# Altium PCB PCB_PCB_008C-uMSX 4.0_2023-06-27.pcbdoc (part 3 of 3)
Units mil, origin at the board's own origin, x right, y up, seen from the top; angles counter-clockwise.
Board outline 14478.11 x 5217.07 mil, 2 copper layers (Top Layer, Bottom Layer); 184 components, 339 nets, 1501 pads, 946 vias.
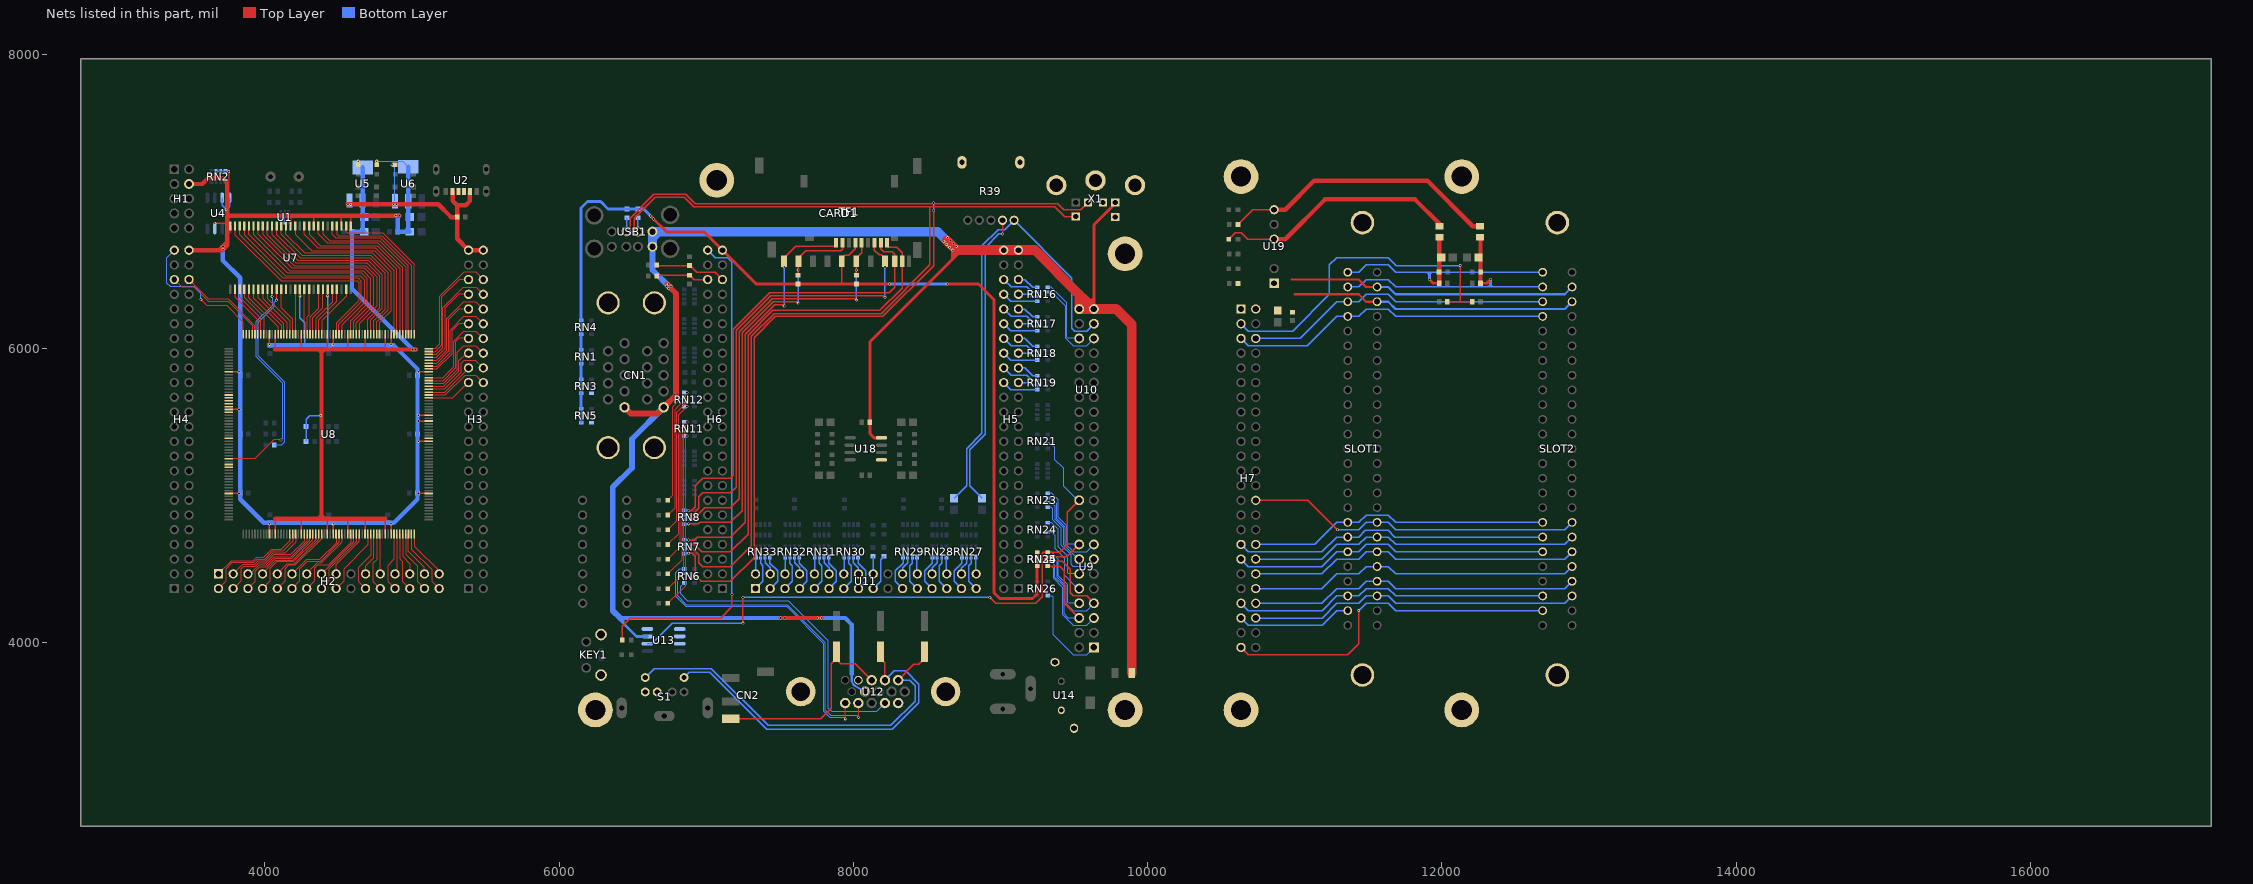
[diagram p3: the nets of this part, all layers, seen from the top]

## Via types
v1: diameter 20, hole 12, Top Layer to Bottom Layer, 944 vias
v2: diameter 24, hole 12, Top Layer to Bottom Layer, 2 vias

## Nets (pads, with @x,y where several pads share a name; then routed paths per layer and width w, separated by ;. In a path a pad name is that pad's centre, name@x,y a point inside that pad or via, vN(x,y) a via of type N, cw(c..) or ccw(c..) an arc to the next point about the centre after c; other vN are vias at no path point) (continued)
IO/163: H3.29 H5.30 RN19.1 U8.163 | length 561
  Top Layer w6: U8.163@5114.14,5663.11 5276.92,5663.11 5380.86,5767.05 H3.29@5385,5767.05
  Bottom Layer w10: H5.30@9022.01,5767.05 9069.25,5719.81 RN19.1@9249.57,5719.81
IO/164: H3.30 H5.29 RN19.2 U8.164 | length 581.3
  Top Layer w6: U8.164@5114.14,5682.8 5226.51,5682.8 5360.76,5817.05 5435,5817.05 H3.30@5485,5767.05
  Bottom Layer w10: H5.29@9122.01,5767.05 9192.01,5767.05 9207.76,5751.3 RN19.2@9249.57,5751.3
IO/165: H3.31 H5.32 RN19.3 U8.165 | length 603.3
  Top Layer w6: U8.165@5114.14,5702.48 5223.57,5702.48 5385,5863.91 H3.31@5385,5867.05
  Bottom Layer w10: H5.32@9022.01,5867.05 9072.01,5817.05 9180,5817.05 9214.25,5782.8 RN19.3@9249.57,5782.8
IO/166: H3.32 H5.31 RN19.4 U8.166 | length 658.4
  Top Layer w6: U8.166@5114.14,5722.17 5220.63,5722.17 5331,5832.54 5331,5895.22 5352.83,5917.05 5435,5917.05 H3.32@5485,5867.05
  Bottom Layer w10: H5.31@9122.01,5867.05 9165,5867.05 9217.76,5814.29 RN19.4@9249.57,5814.29
IO/167: H3.33 H5.34 RN18.1 U8.167 | length 653.5
  Top Layer w6: U8.167@5114.14,5741.85 5217.68,5741.85 5319,5843.17 5319,5915.19 5370.86,5967.05 H3.33@5385,5967.05
  Bottom Layer w10: H5.34@9022.01,5967.05 9069.25,5919.81 RN18.1@9249.57,5919.81
IO/168: H3.34 H5.33 RN18.2 U8.168 | length 700.8
  Top Layer w6: U8.168@5114.14,5761.54 5214.74,5761.54 5307,5853.79 5307,5972.08 5351.97,6017.05 5435,6017.05 H3.34@5485,5967.05
  Bottom Layer w10: H5.33@9122.01,5967.05 9192.01,5967.05 9207.76,5951.3 RN18.2@9249.57,5951.3
IO/169: H3.35 H5.36 RN18.3 U8.169 | length 756.4
  Top Layer w6: U8.169@5114.14,5781.22 5211.8,5781.22 5295,5864.42 5295,6043.11 5318.94,6067.05 H3.35@5385,6067.05
  Bottom Layer w10: H5.36@9022.01,6067.05 9072.01,6017.05 9180,6017.05 9214.25,5982.8 RN18.3@9249.57,5982.8
IO/170: H3.36 H5.35 RN18.4 U8.170 | length 773.3
  Top Layer w6: U8.170@5114.14,5800.91 5208.86,5800.91 5283,5875.05 5283,6048.08 5351.97,6117.05 5435,6117.05 H3.36@5485,6067.05
  Bottom Layer w10: H5.35@9122.01,6067.05 9165,6067.05 9217.76,6014.29 RN18.4@9249.57,6014.29
IO/173: H3.37 H5.38 RN17.1 U8.173 | length 737.8
  Top Layer w6: U8.173@5114.14,5859.96 5169.88,5859.96 5271,5961.08 5271,6119.11 5318.94,6167.05 H3.37@5385,6167.05
  Bottom Layer w10: H5.38@9022.01,6167.05 9069.25,6119.81 RN17.1@9249.57,6119.81
IO/174: H3.38 H5.37 RN17.2 U8.174 | length 755.1
  Top Layer w6: U8.174@5114.14,5879.65 5167.6,5879.65 5259,5971.05 5259,6124.08 5351.97,6217.05 5435,6217.05 H3.38@5485,6167.05
  Bottom Layer w10: H5.37@9122.01,6167.05 9192.01,6167.05 9207.76,6151.3 RN17.2@9249.57,6151.3
IO/175: H3.39 H5.40 RN17.3 U8.175 | length 812.2
  Top Layer w6: U8.175@5114.14,5899.33 5167.28,5899.33 5247,5979.05 5247,6195.11 5318.94,6267.05 H3.39@5385,6267.05
  Bottom Layer w10: H5.40@9022.01,6267.05 9072.01,6217.05 9180,6217.05 9214.25,6182.8 RN17.3@9249.57,6182.8
IO/176: H3.40 H5.39 RN17.4 U8.176 | length 830.6
  Top Layer w6: U8.176@5114.14,5919.02 5166.97,5919.02 5235,5987.05 5235,6200.08 5351.97,6317.05 5435,6317.05 H3.40@5485,6267.05
  Bottom Layer w10: H5.39@9122.01,6267.05 9165,6267.05 9217.76,6214.29 RN17.4@9249.57,6214.29
IO/177: H3.41 H5.42 RN16.1 U8.177 | length 856
  Top Layer w6: U8.177@5114.14,5938.7 5164.68,5938.7 5223,5997.02 5223,6271.11 5318.94,6367.05 H3.41@5385,6367.05
  Bottom Layer w10: H5.42@9022.01,6367.05 9069.25,6319.81 RN16.1@9249.57,6319.81
IO/178: H3.42 H5.41 RN16.2 U8.178 | length 871.9
  Top Layer w6: U8.178@5114.14,5958.39 5164.37,5958.39 5211,6005.02 5211,6276.08 5348.97,6414.05 5438,6414.05 H3.42@5485,6367.05
  Bottom Layer w10: H5.41@9122.01,6367.05 9192.01,6367.05 9207.76,6351.3 RN16.2@9249.57,6351.3
IO/179: H3.43 H5.44 RN16.3 U8.179 | length 928.6
  Top Layer w6: U8.179@5114.14,5978.07 5160.05,5978.07 5199,6017.02 5199,6346.08 5319.97,6467.05 H3.43@5385,6467.05
  Bottom Layer w10: H5.44@9022.01,6467.05 9072.01,6417.05 9180,6417.05 9214.25,6382.8 RN16.3@9249.57,6382.8
IO/180: H3.44 H5.43 RN16.4 U8.180 | length 945.7
  Top Layer w6: U8.180@5114.14,5997.76 5158.74,5997.76 5187,6026.02 5187,6351.05 5352,6516.05 5436,6516.05 H3.44@5485,6467.05
  Bottom Layer w10: H5.43@9122.01,6467.05 9165,6467.05 9217.76,6414.29 RN16.4@9249.57,6414.29
IORQ: H7.38 RN24.5 SLOT1.11 SLOT2.11 U9.12 | length 2748.5
  Bottom Layer w6: RN24.5@9320.43,4814.29 9347.76,4814.29 9392.03,4770.02 9392.03,4650.93 9456,4586.96 9456,4473.05 9462,4467.05 U9.12@9535,4467.05
  Bottom Layer w10: H7.38@10735,4467.05 11185,4467.05 11285,4567.05 11435,4567.05 11485.03,4617.08 SLOT1.11@11560,4617.08 11634.97,4617.08 11685,4567.05 12834.97,4567.05 SLOT2.11@12885,4617.08
KCLK: R14.1 RN7.5 USB1.7 X1.1 | length 7481.1
  Top Layer w10: USB1.7@6457.61,6793.1 6482.61,6818.1 6482.61,6884.66 6645,7047.05 6860,7047.05 6925,6982.05 9389.99,6982.05 9429.99,6942.05 9546.01,6942.05 X1.1@9595.01,6991.05 ; v1(6880,4607.05) 6905,4607.05 6925,4587.05 6925,4457.05 6965,4417.05 7165,4417.05 7325,4577.05 7325,6072.05 7470,6217.05 8200,6217.05 8545,6562.05 v1(8545,6937.05)
  Bottom Layer w10: USB1.7@6457.61,6793.1 6460,6795.49 R14.1@6460,6887.39 ; RN7.5@6849.56,4604.81 6851.81,4607.05 v1(6880,4607.05) ; v1(8545,6937.05) v1(8545,6987.05)
KDAT: R15.1 RN7.6 USB1.6 X1.6 | length 7140.9
  Top Layer w10: USB1.6@6536.41,6793.1 6511.41,6818.1 6511.41,6883.46 6655,7027.05 6850,7027.05 6915,6962.05 9370,6962.05 9437,6895.05 X1.6@9512.01,6895.05 ; v1(6880,4637.05) 6910,4637.05 6950,4597.05 6950,4542.05 6975,4517.05 7165,4517.05 7305,4657.05 7305,6080.33 7460.86,6236.19 8189.14,6236.19 8520,6567.05 8520,6962.05
  Bottom Layer w10: R15.1@6535,6887.39 6535,6794.51 USB1.6@6536.41,6793.1 ; RN7.6@6849.56,4636.3 6850.31,4637.05 v1(6880,4637.05)
LED1: LED5.2 RN12.8 | length 786.3
  Top Layer w6: LED5.2@6739.5,4966.85 6773,5000.35 6773,5602.72 v1(6869.56,5699.29)
LED2: LED6.2 RN12.7 | length 854.8
  Top Layer w6: LED6.2@6739.5,4866.85 6785,4912.35 6785,5583.23 v1(6869.56,5667.8)
LED3: LED7.2 RN12.6 | length 923.3
  Top Layer w6: LED7.2@6739.5,4766.85 6797,4824.35 6797,5563.73 v1(6869.56,5636.3)
LED4: LED8.2 RN12.5 | length 991.8
  Top Layer w6: LED8.2@6739.5,4666.85 6809,4736.35 6809,5544.24 v1(6869.56,5604.81)
LED5: LED9.2 RN11.8 | length 986.3
  Top Layer w6: LED9.2@6739.5,4566.85 6821,4648.35 6821,5450.72 v1(6869.56,5499.29)
LED6: LED10.2 RN11.7 | length 1054.8
  Top Layer w6: LED10.2@6739.5,4466.85 6833,4560.35 6833,5431.23 v1(6869.56,5467.8)
LED7: LED11.2 RN11.6 | length 1123.3
  Top Layer w6: LED11.2@6739.5,4366.85 6845,4472.35 6845,5411.73 v1(6869.56,5436.3)
LED8: LED12.2 RN11.5 | length 1191.8
  Top Layer w6: LED12.2@6739.5,4266.85 6857,4384.35 6857,5392.24 v1(6869.56,5404.81)
M1: H7.40 RN24.7 SLOT1.9 SLOT2.9 U9.10 | length 2747.2
  Bottom Layer w6: RN24.7@9320.43,4751.3 9346.96,4751.3 9368.03,4730.22 9368.03,4640.99 9432,4577.02 9432,4461.56 9526.51,4367.05 U9.10@9535,4367.05
  Bottom Layer w10: H7.40@10735,4367.05 11185,4367.05 11285,4467.05 11435,4467.05 11485.03,4517.08 SLOT1.9@11560,4517.08 11634.97,4517.08 11685,4467.05 12834.97,4467.05 SLOT2.9@12885,4517.08
MA0: U7.23 U8.203 | length 1409.9
  Top Layer w6: U7.23@3891.95,6832.05 3891.95,6774.13 4156.03,6510.05 4657.91,6510.05 4696,6471.96 4696,6302.14 4582.64,6188.77 U8.203@4582.64,6096.18
MA1: U7.24 U8.206 | length 1435.6
  Top Layer w6: U7.24@3859.97,6832.05 3859.97,6772.08 4139,6493.05 4647.94,6493.05 4676.5,6464.49 4676.5,6309.61 4523.57,6156.68 U8.206@4523.57,6096.18
MA2: U7.25 U8.207 | length 1442.2
  Top Layer w6: U7.25@3828.95,6832.05 3828.95,6773.1 4125,6477.05 4636.97,6477.05 4657,6457.02 4657,6317.08 4503.9,6163.97 U8.207@4503.9,6096.18
MA3: U7.26 U8.208 | length 1450.4
  Top Layer w6: U7.26@3796.95,6832.05 3796.95,6773.13 4110.03,6460.05 4627,6460.05 4637.5,6449.55 4637.5,6324.55 4484.2,6171.25 U8.208@4484.2,6096.18
MA4: U7.29 U8.235 | length 370.4
  Top Layer w6: U7.29@3797,6402.05 3797,6350.05 3952.72,6194.33 U8.235@3952.72,6096.18
MA5: U7.30 U8.234 | length 365.3
  Top Layer w6: U7.30@3829,6402.05 3829,6348.05 3972.41,6204.64 U8.234@3972.41,6096.18
MA6: U7.31 U8.233 | length 360.6
  Top Layer w6: U7.31@3859.97,6402.05 3859.97,6347.08 3992.09,6214.96 U8.233@3992.09,6096.18
MA7: U7.32 U8.228 | length 388.1
  Top Layer w6: U7.32@3892,6402.05 3892,6345.05 4090.51,6146.53 U8.228@4090.51,6096.18
MA8: U7.33 U8.227 | length 383.4
  Top Layer w6: U7.33@3923,6402.05 3923,6344.05 4110.19,6156.85 U8.227@4110.19,6096.18
MA9: U7.34 U8.226 | length 378.3
  Top Layer w6: U7.34@3954.97,6402.05 3954.97,6342.08 4129.89,6167.16 U8.226@4129.89,6096.18
MA10: U7.22 U8.202 | length 1404.2
  Top Layer w6: U7.22@3923,6832.05 3923,6775.05 4171,6527.05 4667.88,6527.05 4718,6476.93 4718,6297.17 4602.31,6181.48 U8.202@4602.31,6096.18
MA11: U7.35 U8.225 | length 373.6
  Top Layer w6: U7.35@3986.05,6402.05 3986.05,6341 4149.56,6177.48 U8.225@4149.56,6096.18
MA12: U7.36 U8.224 | length 368.5
  Top Layer w6: U7.36@4018,6402.05 4018,6339.05 4169.26,6187.79 U8.224@4169.26,6096.18
MBA0: U7.20 U8.200 | length 1389.7
  Top Layer w6: U7.20@3986.05,6832.05 3986.05,6775.08 4201.08,6560.05 4687,6560.05 4759.5,6487.55 4759.5,6284.72 4641.69,6166.91 U8.200@4641.69,6096.18
MBA1: U7.21 U8.201 | length 1398
  Top Layer w6: U7.21@3954.97,6832.05 3954.97,6775.11 4187.03,6543.05 4678.85,6543.05 4740,6481.9 4740,6292.2 4622.01,6174.2 U8.201@4622.01,6096.18
MCAS: U7.17 U8.195 | length 1352.1
  Top Layer w6: U7.17@4081.05,6832.05 4081.05,6773.05 4243.05,6611.05 4716.91,6611.05 4819.37,6508.59 4819.37,6266.42 4740.11,6187.16 U8.195@4740.11,6096.18
MCKE: U7.37 U8.39 | length 1556.6
  Top Layer w6: U8.39@3755.86,5249.73 3932.68,5249.73 4060,5377.05 v1(4110,5377.05) ; U7.37@4049,6402.05 4050,6401.05 v1(4050,6352.05)
  Bottom Layer w6: v1(4050,6352.05) 4050,6289.02 3940,6179.02 3940,5947.05 4120,5767.05 4120,5387.05 v1(4110,5377.05)
MCLK: R13.2 U7.38 | length 1243.6
  Top Layer w6: v1(4080,6327.05) 4081.05,6328.1 U7.38@4081.05,6402.05
  Bottom Layer w6: R13.2@4064.66,5342.05 4111.87,5342.05 4132,5362.18 4132,5772.02 3952,5952.02 3952,6174.05 4062,6284.05 4062,6309.05 v1(4080,6327.05)
MCS: U7.19 U8.197 | length 1367.2
  Top Layer w6: U7.19@4018,6832.05 4018,6773.05 4214,6577.05 4696.97,6577.05 4780,6494.02 4780,6277.05 4700.74,6197.79 U8.197@4700.74,6096.18
MD0: U7.2 U8.181 | length 1068.7
  Top Layer w6: U7.2@4553,6832.05 4553,6793.05 4564,6782.05 4805,6782.05 5015.7,6571.34 U8.181@5015.7,6096.18
MD1: U7.4 U8.182 | length 1118.6
  Top Layer w6: U7.4@4489.97,6832.05 4489.97,6776.05 4500.97,6765.05 4796.47,6765.05 4996.02,6565.5 U8.182@4996.02,6096.18
MD2: U7.5 U8.183 | length 1129.2
  Top Layer w6: U7.5@4458,6832.05 4458,6774.05 4484,6748.05 4789,6748.05 4976.34,6560.71 U8.183@4976.34,6096.18
MD3: U7.7 U8.184 | length 1167.7
  Top Layer w6: U7.7@4394.97,6832.05 4394.97,6777.05 4440.97,6731.05 4781,6731.05 4956.65,6555.4 U8.184@4956.65,6096.18
MD4: U7.8 U8.185 | length 1174.6
  Top Layer w6: U7.8@4364,6832.05 4364,6778.05 4428,6714.05 4771.85,6714.05 4936.97,6548.94 U8.185@4936.97,6096.18
MD5: U7.10 U8.186 | length 1216.9
  Top Layer w6: U7.10@4301.05,6832.05 4301.05,6773.97 4377.97,6697.05 4763.32,6697.05 4917.27,6543.1 U8.186@4917.27,6096.18
MD6: U7.11 U8.187 | length 1224.9
  Top Layer w6: U7.11@4269,6832.05 4269,6774.05 4363,6680.05 4753.35,6680.05 4897.6,6535.81 U8.187@4897.6,6096.18
MD7: U7.13 U8.188 | length 1265.1
  Top Layer w6: U7.13@4206.05,6832.05 4206.05,6774.05 4318.05,6662.05 4746.35,6662.05 4877.9,6530.5 U8.188@4877.9,6096.18
MD8: U7.42 U8.222 | length 306.9
  Top Layer w6: U7.42@4206.05,6402.05 4208.62,6399.47 U8.222@4208.62,6096.18
MD9: U7.44 U8.219 | length 306.4
  Top Layer w6: U8.219@4267.68,6096.18 4267.68,6400.72 U7.44@4269,6402.05
MD10: U7.45 U8.218 | length 311.5
  Top Layer w6: U8.218@4287.36,6096.18 4287.36,6214.41 4301.05,6228.1 U7.45@4301.05,6402.05
MD11: U7.47 U8.217 | length 329.5
  Top Layer w6: U8.217@4307.05,6096.18 4307.05,6211.46 4364,6268.41 U7.47@4364,6402.05
MD12: U7.48 U8.216 | length 334.1
  Top Layer w6: U8.216@4326.73,6096.18 4326.73,6206.15 4394.97,6274.38 U7.48@4394.97,6402.05
MD13: U7.50 U8.215 | length 352.1
  Top Layer w6: U8.215@4346.41,6096.18 4346.41,6200.83 4458,6312.41 U7.50@4458,6402.05
MD14: U7.51 U8.214 | length 357.2
  Top Layer w6: U8.214@4366.1,6096.18 4366.1,6195.52 4489.97,6319.38 U7.51@4489.97,6402.05
MD15: U7.53 U8.213 | length 375.1
  Top Layer w6: U8.213@4385.78,6096.18 4385.78,6187.83 4553,6355.05 U7.53@4553,6402.05
MERQ: H7.35 RN23.8 SLOT1.12 SLOT2.12 U9.13 | length 2803.7
  Bottom Layer w6: RN23.8@9320.43,4919.81 9345.03,4919.81 9356.03,4908.81 9356.03,4836.02 9414.01,4778.03 9414.01,4662.58 9480.03,4596.56 9480.03,4532.02 9495,4517.05 9585,4517.05 U9.13@9635,4567.05
  Bottom Layer w10: H7.35@10635,4567.05 10685,4517.05 11185,4517.05 11285.03,4617.08 SLOT1.12@11360,4617.08 11435.03,4617.08 11485,4667.05 11635,4667.05 11684.97,4617.08 SLOT2.12@12685,4617.08
MLDQ: U7.15 U8.193 | length 1334.5
  Top Layer w6: U7.15@4144,6832.05 4144,6775.05 4274,6645.05 4734.5,6645.05 4858.74,6520.81 4858.74,6256.42 4779.48,6177.16 U8.193@4779.48,6096.18
MRAS: U7.18 U8.196 | length 1361.4
  Top Layer w6: U7.18@4049,6832.05 4049,6771.05 4226,6594.05 4706.94,6594.05 4799.68,6501.31 4799.68,6272.05 4720.43,6192.79 U8.196@4720.43,6096.18
MUDQ: U7.39 U8.223 | length 337.7
  Top Layer w6: U7.39@4112,6402.05 4112,6275.05 4188.94,6198.11 U8.223@4188.94,6096.18
MWE: U7.16 U8.194 | length 1342.5
  Top Layer w6: U7.16@4112,6832.05 4112,6775.05 4259,6628.05 4724.38,6628.05 4839.05,6513.38 4839.05,6261.42 4759.8,6182.16 U8.194@4759.8,6096.18
PWRLED: H4.47 H6.48 R34.1 U8.240 | length 4419.5
  Top Layer w6: v1(3565,6332.05) 3605,6292.05 3740,6292.05 3854.3,6177.75 U8.240@3854.3,6096.18
  Top Layer w10: R34.1@6430.34,4017.05 6430,4017.39 6430,4112.05 6485,4167.05 7100,4167.05 7175,4242.05 v1(7175,4327.05)
  Bottom Layer w6: H4.47@3385,6667.05 3335,6617.05 3335,6442.05 3360,6417.05 3525,6417.05 3565,6377.05 v1(3565,6332.05)
  Bottom Layer w10: H6.48@7010,6667.05 7060,6617.05 7145,6617.05 7175,6587.05 v1(7175,4327.05)
RD: H7.33 RN23.6 SLOT1.14 SLOT2.14 U9.15 | length 2807
  Bottom Layer w6: RN23.6@9320.43,4982.8 9345.91,4982.8 9380.03,4948.68 9380.03,4845.96 9438.01,4787.97 9438.01,4675.86 9496.82,4617.05 9585,4617.05 U9.15@9635,4667.05
  Bottom Layer w10: H7.33@10635,4667.05 10685,4617.05 11185,4617.05 11285,4717.05 11360,4717.05 11404.94,4717.05 ; SLOT1.14@11360,4717.08 11404.94,4717.08 11435.03,4717.08 11480,4762.05 11635.03,4762.05 11680,4717.08 SLOT2.14@12685,4717.08
RESET: H7.28 RN21.7 RN34.4 SLOT1.15 SLOT2.15 U9.22 U13.6 | length 6564.4
  Top Layer w10: v1(7250,4132.05) v1(7250,4307.05) ; v1(8927.5,4307.05) 8967.5,4267.05 9240,4267.05 9285,4312.05 9285,4607.05 9292.24,4614.29 RN34.4@9320.43,4614.29 9402.24,4614.29 9455,4667.05 9455,4887.05 U9.22@9535,4967.05 ; H7.28@10735,4967.05 11090,4967.05 v1(11290,4767.05)
  Bottom Layer w6: RN21.7@9320.43,5351.3 9346,5351.3 9367,5330.3 9367,5247.02 9427,5187.02 9427,5066.56 9526.51,4967.05 U9.22@9535,4967.05
  Bottom Layer w10: U13.6@6599.92,3992.05 6630,3992.05 6770,4132.05 v1(7250,4132.05) ; v1(7250,4307.05) v1(8927.5,4307.05) ; v1(11290,4767.05) 11435,4767.05 11485.03,4817.08 SLOT1.15@11560,4817.08 11634.97,4817.08 11685,4767.05 12834.97,4767.05 SLOT2.15@12885,4817.08
RFSH: H7.41 RN25.6 RN34.2 SLOT1.6 SLOT2.6 U9.7 | length 3339
  Top Layer w10: RN34.2@9320.43,4551.3 9420.75,4551.3 9475,4497.05 9475,4337.05 9495,4317.05 9585,4317.05 U9.7@9635,4267.05
  Bottom Layer w6: RN25.6@9320.43,4582.8 9347.28,4582.8 9382,4548.08 9382,4448.99 9444,4386.99 9444,4268.05 9495,4217.05 9585,4217.05 U9.7@9635,4267.05
  Bottom Layer w10: H7.41@10635,4267.05 10685,4217.05 11186.97,4217.05 11286.97,4317.05 11360,4317.05 11404.94,4317.05 ; SLOT1.6@11360,4317.08 11404.94,4317.08 11435.03,4317.08 11485,4367.05 11635,4367.05 11684.97,4317.08 SLOT2.6@12685,4317.08
RSV5: H7.44 RN25.7 RN34.1 SLOT1.5 SLOT2.5 U9.6 | length 3273.9
  Top Layer w10: RN34.1@9320.43,4519.81 9402.24,4519.81 9435,4487.05 9435,4267.05 U9.6@9535,4167.05
  Bottom Layer w6: RN25.7@9320.43,4551.3 9345.75,4551.3 9370,4527.05 9370,4444.02 9432,4382.02 9432,4197.02 9461.97,4167.05 U9.6@9535,4167.05
  Bottom Layer w10: H7.44@10735,4167.05 11186.97,4167.05 11286.97,4267.05 11435,4267.05 11485.03,4317.08 SLOT1.5@11560,4317.08 11634.97,4317.08 11685,4267.05 12834.97,4267.05 SLOT2.5@12885,4317.08
RSV16: H7.34 RN23.5 RN34.3 SLOT1.16 SLOT2.16 U9.16 | length 2796.8
  Top Layer w10: RN34.3@9320.43,4582.8 9450.75,4582.8 U9.16@9535,4667.05
  Bottom Layer w6: RN23.5@9320.43,5014.29 9347.76,5014.29 9392.03,4970.02 9392.03,4850.93 9450.01,4792.94 9450.01,4680.83 9463.79,4667.05 U9.16@9535,4667.05
  Bottom Layer w10: H7.34@10735,4667.05 11136.97,4667.05 11287,4817.08 SLOT1.16@11360,4817.08 11435.03,4817.08 11485,4867.05 11635,4867.05 11684.97,4817.08 SLOT2.16@12685,4817.08
SCLK: RN6.5 U12.12 | length 2097.6
  Bottom Layer w6: RN6.5@6849.56,4404.81 6826,4381.24 6826,4331.96 6875.91,4282.05 7560.91,4282.05 7831,4011.96 7831,3553.02 7854.97,3529.05 8154.68,3529.05 U12.12@8214.74,3589.1
SD_CK: CARD1.5 R30.1 RN8.6 TF1.5 | length 2903.8
  Top Layer w10: v1(6880,4837.05) 6910,4837.05 6990,4917.05 7165,4917.05 7225,4977.05 7225,6113.47 7448.58,6337.05 8010,6337.05 v1(8020,6327.05) ; R30.1@8020,6496.71 v1(8020,6532.05) 8020,6613.23 8056.66,6649.89 TF1.5@8056.66,6718.39
  Bottom Layer w10: RN8.6@6849.56,4836.3 6850.31,4837.05 v1(6880,4837.05) ; v1(8020,6327.05) v1(8020,6532.05)
SD_CM: CARD1.1 R29.1 RN8.5 TF1.2 | length 2823.9
  Top Layer w10: v1(6880,4807.05) 6945,4807.05 6955,4817.05 7165,4817.05 7245,4897.05 7245,6105.19 7456.86,6317.05 7615,6317.05 v1(7625,6307.05) ; R29.1@7625,6496.71 v1(7625,6532.05) 7625,6589.73 CARD1.1@7626.53,6591.26 7626.53,6611.26 7677.32,6662.05 7913.89,6662.05 7926.74,6674.89 TF1.2@7926.74,6718.39
  Bottom Layer w10: RN8.5@6849.56,4804.81 6851.81,4807.05 v1(6880,4807.05) ; v1(7625,6307.05) v1(7625,6532.05)
SD_D0: CARD1.7 RN8.7 TF1.7 | length 3027.5
  Top Layer w10: v1(6880,4867.05) 6905,4867.05 6950,4912.05 6950,4992.05 6975,5017.05 7165,5017.05 7205,5057.05 7205,6121.75 7440.29,6357.05 8205,6357.05 v1(8215,6347.05) ; TF1.7@8143.27,6718.39 8143.27,6668.18 8175.19,6636.26 8189.33,6636.26 8214.33,6611.26 CARD1.7@8214.33,6591.26
  Bottom Layer w10: RN8.7@6849.56,4867.8 6879.25,4867.8 v1(6880,4867.05) ; v1(8215,6347.05) v1(8215,6552.05)
SD_D1: CARD1.8 RN8.8 TF1.8 | length 3104.3
  Top Layer w10: v1(6880,4897.05) 6900,4897.05 6925,4922.05 6925,5067.05 6975,5117.05 7165,5117.05 7185,5137.05 7185,6130.04 7432.01,6377.05 8242.5,6377.05 8281.25,6415.8 CARD1.8@8281.25,6591.26 8281.25,6640.8 8265,6657.05 8206.58,6657.05 8186.58,6677.05 TF1.8@8186.58,6718.39
  Bottom Layer w10: RN8.8@6849.56,4899.29 6877.76,4899.29 v1(6880,4897.05)
SD_D2: CARD1.10 RN7.7 TF1.CD | length 3418.7
  Top Layer w10: v1(6880,4667.05) 6920,4667.05 6970,4617.05 7165,4617.05 7285,4737.05 7285,6088.62 7453.43,6257.05 8180,6257.05 8332.43,6409.48 CARD1.10@8332.43,6591.26 8332.43,6649.62 8295,6687.05 8245,6687.05 8229.89,6702.16 TF1.CD@8229.89,6718.39
  Bottom Layer w10: RN7.7@6849.56,4667.8 6879.25,4667.8 v1(6880,4667.05)
SD_D3: CARD1.9 RN7.8 TF1.1 | length 2791.5
  Top Layer w10: v1(6880,4697.05) 6920,4697.05 6940,4717.05 7165,4717.05 7265,4817.05 7265,6096.9 7465.15,6297.05 7520,6297.05 v1(7530,6287.05) ; CARD1.9@7528.1,6591.26 7528.1,6611.26 7608.89,6692.05 7872.09,6692.05 7883.43,6703.39 TF1.1@7883.43,6718.39
  Bottom Layer w10: RN7.8@6849.56,4699.29 6851.81,4697.05 v1(6880,4697.05) ; v1(7530,6287.05) v1(7530,6552.05)
SDAT: RN6.8 U12.15 | length 2102.9
  Top Layer w6: U12.15@7944.25,3589.1 7945,3588.35 v1(7945,3482.05)
  Bottom Layer w6: RN6.8@6849.56,4499.29 6817.24,4499.29 6790,4472.05 6790,4317.05 6861,4246.05 7546,4246.05 7795,3997.05 7795,3538.11 7840.06,3493.05 7934,3493.05 v1(7945,3482.05)
SL0: H2.22 RN29.4 U8.105 U11.21 | length 684.1
  Top Layer w6: H2.22@4685,4367.05 4635,4417.05 4635,4508.11 4720.43,4593.53 U8.105@4720.43,4737.92
  Bottom Layer w10: U11.21@8335,4367.05 8285,4417.05 8285,4487.05 8337.76,4539.81 RN29.4@8337.76,4581.61
SL1: H2.21 RN29.3 U8.106 U11.22 | length 422.5
  Top Layer w6: H2.21@4685,4467.05 4685,4521.14 4740.11,4576.25 U8.106@4740.11,4737.92
  Bottom Layer w10: U11.22@8335,4467.05 8335,4507.05 8369.25,4541.3 RN29.3@8369.25,4581.61
SL2: H2.24 RN29.2 U8.107 U11.23 | length 643.7
  Top Layer w6: U8.107@4759.8,4737.92 4759.8,4563.96 4735,4539.17 4735,4417.05 H2.24@4785,4367.05
  Bottom Layer w10: RN29.2@8400.75,4581.61 8400.75,4537.8 8385,4522.05 8385,4417.05 U11.23@8435,4367.05
SL3: H2.23 RN29.1 U8.108 U11.24 | length 388.9
  Top Layer w6: U8.108@4779.48,4737.92 4779.48,4472.56 H2.23@4785,4467.05
  Bottom Layer w10: RN29.1@8432.24,4581.61 8432.24,4469.81 U11.24@8435,4467.05
SL4: H2.26 RN28.4 U8.113 U11.25 | length 666.5
  Top Layer w6: U8.113@4877.9,4737.92 4877.9,4564.95 4835,4522.05 4835,4417.05 H2.26@4885,4367.05
  Bottom Layer w10: U11.25@8535,4367.05 8485,4417.05 8485,4487.05 8537.76,4539.81 RN28.4@8537.76,4581.61
SL5: H2.25 RN28.3 U8.114 U11.26 | length 404.8
  Top Layer w6: H2.25@4885,4467.05 4897.6,4479.64 U8.114@4897.6,4737.92
  Bottom Layer w10: U11.26@8535,4467.05 8535,4507.05 8569.25,4541.3 RN28.3@8569.25,4581.61
SLTSL1: H7.43 RN25.8 SLOT1.4 U9.5 | length 1438.5
  Bottom Layer w6: RN25.8@9320.43,4519.81 9347,4519.81 9358,4508.81 9358,4439.05 9420,4377.05 9420,4192.05 9495,4117.05 9585,4117.05 U9.5@9635,4167.05
  Bottom Layer w10: H7.43@10635,4167.05 10685,4117.05 11186.97,4117.05 11286.97,4217.05 SLOT1.4@11360,4217.05
SLTSL2: H7.47 RN26.8 SLOT2.4 U9.1 | length 3019.7
  Top Layer w10: H7.47@10635,3967.05 10685,3917.05 11360,3917.05 11435,3992.05 v1(11435,4217.05)
  Bottom Layer w6: RN26.8@9320.43,4319.81 9347.24,4319.81 9355,4312.05 9355,4057.05 9495,3917.05 9585,3917.05 U9.1@9635,3967.05
  Bottom Layer w10: v1(11435,4217.05) 11485.01,4267.05 11635,4267.05 11684.97,4217.08 SLOT2.4@12685,4217.08
SOUND_L: C26.1 C36.1 C37.1 H7.3 R39.5 U10.21 | length 5431.2
  Top Layer w10: C36.1@12037.55,6317.05 12125.76,6317.05 ; v1(12125,6562.05) 12125,6317.81 12125.76,6317.05 ; C37.1@12207.45,6317.05 12125.76,6317.05
  Bottom Layer w10: C26.1@8685,4981.42 8770,5066.42 8770,5317.05 8874,5421.05 8874,6696.05 8985.48,6807.53 9029.81,6807.53 R39.5@9092.48,6870.19 9485,6477.68 9485,6137.05 9505,6117.05 9585,6117.05 U10.21@9635,6167.05 ; H7.3@10635,6167.05 10685,6117.05 10985,6117.05 11235,6367.05 11235,6567.05 11285,6617.05 11635,6617.05 11690,6562.05 v1(12125,6562.05)
SOUND_R: C25.1 R39.3 | length 2034.1
  Top Layer w10: R39.3@9013.74,6870.19 9015,6868.94 v1(9015,6777.05)
  Bottom Layer w10: C25.1@8875,4981.42 8790,5066.42 8790,5309.42 8895,5414.42 8895,6685.09 8986.96,6777.05 v1(9015,6777.05)
SR0: H2.28 RN28.2 U8.115 U11.27 | length 640.7
  Top Layer w6: U8.115@4917.27,4737.92 4917.27,4569.77 4935,4552.05 4935,4417.05 H2.28@4985,4367.05
  Bottom Layer w10: RN28.2@8600.75,4581.61 8600.75,4537.8 8585,4522.05 8585,4417.05 U11.27@8635,4367.05
SR1: H2.27 RN28.1 U8.116 U11.28 | length 406.5
  Top Layer w6: U8.116@4936.97,4737.92 4936.97,4585.08 4985,4537.05 H2.27@4985,4467.05
  Bottom Layer w10: RN28.1@8632.24,4581.61 8632.24,4469.81 U11.28@8635,4467.05
SR2: H2.30 RN27.4 U8.117 U11.29 | length 681.2
  Top Layer w6: U8.117@4956.65,4737.92 4956.65,4600.4 5035,4522.05 5035,4417.05 H2.30@5085,4367.05
  Bottom Layer w10: U11.29@8735,4367.05 8685,4417.05 8685,4487.05 8737.76,4539.81 RN27.4@8737.76,4581.61
SR3: H2.29 RN27.3 U8.118 U11.30 | length 444.6
  Top Layer w6: U8.118@4976.34,4737.92 4976.34,4620.71 5085,4512.05 H2.29@5085,4467.05
  Bottom Layer w10: U11.30@8735,4467.05 8735,4505.24 8769.25,4539.49 RN27.3@8769.25,4581.61
SR4: H2.32 RN27.2 U8.119 U11.31 | length 690.9
  Top Layer w6: U8.119@4996.02,4737.92 4996.02,4636.03 5135,4497.05 5135,4417.05 H2.32@5185,4367.05
  Bottom Layer w10: RN27.2@8800.75,4581.61 8800.75,4539.06 8785,4523.31 8785,4417.05 U11.31@8835,4367.05
SR5: H2.31 RN27.1 U8.120 U11.32 | length 456.7
  Top Layer w6: U8.120@5015.7,4737.92 5015.7,4656.34 5185,4487.05 H2.31@5185,4467.05
  Bottom Layer w10: RN27.1@8832.24,4581.61 8832.24,4469.81 U11.32@8835,4467.05
SW1: H7.5 RN16.6 SLOT1.44 SLOT2.44 U10.19 | length 2809.4
  Bottom Layer w6: RN16.6@9320.43,6382.8 9345.7,6382.8 9439,6289.5 9439,6071.53 9493.49,6017.05 9585,6017.05 U10.19@9635,6067.05
  Bottom Layer w10: H7.5@10635,6067.05 10685,6017.05 11085,6017.05 11285.02,6217.07 SLOT1.44@11360,6217.07 11436.02,6217.07 11486,6267.05 11635.02,6267.05 11685,6217.07 SLOT2.44@12685,6217.07
SW2: H7.6 RN16.5 SLOT1.46 SLOT2.46 U10.20 | length 2589.8
  Bottom Layer w6: RN16.5@9320.43,6414.29 9346.18,6414.29 9451,6309.47 9451,6076.5 9460.46,6067.05 U10.20@9535,6067.05
  Bottom Layer w10: H7.6@10735,6067.05 11035.98,6067.05 11286,6317.07 SLOT1.46@11360,6317.07 11435,6317.07 11484.98,6367.05 11635.02,6367.05 11685,6317.07 SLOT2.46@12685,6317.07
USBN1: H4.44 H6.43 R16.1 R22.2 U8.236 | length 1122.3
  Top Layer w6: H4.44@3485,6467.05 3620,6332.05 3755,6332.05 3933.03,6154.01 U8.236@3933.03,6096.18
  Top Layer w10: R16.1@6664.66,6567.05 6669.32,6562.39 R22.2@6885,6562.39 6890,6562.39 6935.34,6517.05 7060,6517.05 H6.43@7110,6467.05
USBP1: H4.43 H6.44 R17.1 R23.2 U8.237 | length 1077
  Top Layer w6: H4.43@3385,6467.05 3435,6417.05 3518.03,6417.05 3615.03,6320.05 3750.03,6320.05 3913.34,6156.73 U8.237@3913.34,6096.18
  Top Layer w10: R17.1@6664.66,6492.05 6669.32,6496.71 R23.2@6885,6496.71 6890.34,6496.71 6920,6467.05 H6.44@7010,6467.05
VB0: H2.1 RN33.4 U8.77 U11.2 | length 738.4
  Top Layer w6: H2.1@3685,4467.05 3771,4553.05 3918.12,4553.05 3941.62,4576.55 3988.74,4576.55 4044.24,4632.05 4108.24,4632.05 4169.24,4693.05 U8.77@4169.24,4737.92
  Bottom Layer w10: U11.2@7335,4467.05 7337.76,4469.81 RN33.4@7337.76,4581.61
VB1: H2.2 RN33.3 U8.78 U11.1 | length 977.3
  Top Layer w6: H2.2@3685,4367.05 3735,4417.05 3735,4500.08 3775.97,4541.05 3923.09,4541.05 3946.59,4564.55 3994.62,4564.55 4050.12,4620.05 4121.03,4620.05 4188.94,4687.95 U8.78@4188.94,4737.92
  Bottom Layer w10: U11.1@7335,4367.05 7385,4417.05 7385,4522.05 7369.25,4537.8 RN33.3@7369.25,4581.61
VB2: H2.3 RN33.2 U8.79 U11.4 | length 698.1
  Top Layer w6: H2.3@3785,4467.05 3847,4529.05 3928.06,4529.05 3951.56,4552.55 3999.59,4552.55 4055.09,4608.05 4136,4608.05 4208.61,4680.66 U8.79@4208.61,4737.92
  Bottom Layer w10: RN33.2@7400.75,4581.61 7400.75,4541.3 7435,4507.05 U11.4@7435,4467.05
VB3: H2.4 RN33.1 U8.82 U11.3 | length 970.3
  Top Layer w6: H2.4@3785,4367.05 3835,4417.05 3835,4500.08 3851.97,4517.05 3933.03,4517.05 3956.53,4540.55 4004.56,4540.55 4060.06,4596.05 4174,4596.05 4267.68,4689.72 U8.82@4267.68,4737.92
  Bottom Layer w10: RN33.1@7432.24,4581.61 7432.24,4539.81 7485,4487.05 7485,4417.05 U11.3@7435,4367.05
VB4: H2.5 RN32.4 U8.83 U11.6 | length 656.9
  Top Layer w6: H2.5@3885,4467.05 3900,4467.05 3961.5,4528.55 4009.53,4528.55 4065.03,4584.05 4178.97,4584.05 4287.35,4692.43 U8.83@4287.35,4737.92
  Bottom Layer w10: U11.6@7535,4467.05 7537.76,4469.81 RN32.4@7537.76,4581.61
VB5: H2.6 RN32.3 U8.84 U11.5 | length 882.4
  Top Layer w6: H2.6@3885,4367.05 3935,4417.05 3935,4485.08 3966.47,4516.55 4014.5,4516.55 4070,4572.05 4183.94,4572.05 4307.05,4695.15 U8.84@4307.05,4737.92
  Bottom Layer w10: U11.5@7535,4367.05 7585,4417.05 7585,4522.05 7569.25,4537.8 RN32.3@7569.25,4581.61
VB_CV: C29.2 CN2.2 U12.3 | length 1467.2
  Top Layer w10: CN2.2@7166.89,3482.6 7167.44,3482.05 7780,3482.05 7850,3552.05 7850,3857.05 C29.2@7884.99,3892.04 ; U12.3@8124.57,3745 8012.52,3857.05 7915,3857.05 7884.99,3887.05 C29.2@7884.99,3892.04 ; C29.2@7884.99,3892.04 C29.2@7884.99,3936.93 7890.1,3936.93 7890.1,3897.15 C29.2@7884.99,3892.04
VCC5: 5V.2@4885.2,7246.55 C7.2 C32.2 C38.2 C39.2 CN1.5 CN1.14 H3.47 H3.48 H5.47 H5.48 H7.1 H7.2 R42.1 SLOT1.45 SLOT1.47 SLOT2.45 SLOT2.47 U2.A9 U2.B9 U5.3 U6.3 U10.23 U10.24 U12.9 U13.7 U15.2 U18.8 U19.1 USB1.1 USB1.5 X1.5 | length 20107.4
  Top Layer w15: 10980,6467.05 11435.02,6467.05 11485,6417.07 SLOT1.47@11560,6417.07 ; 11000,6367.05 11435.02,6367.05 11485,6317.07 SLOT1.45@11560,6317.07
  Top Layer w20: U18.8@8191.39,5391.94 8140.11,5391.94 8112.45,5419.59 8112.45,5496.94 C32.2@8112.56,5497.05 8112.56,6044.61 8675,6607.05 ; v1(8675,6667.05) 8675,6631.89 ; 8700,6667.05 8700,6656.89 8675,6631.89 ; 8735,6667.05 8675,6607.05 ; 9573.65,6328.4 9622.43,6328.4 9635,6340.97 ; U10.23@9635,6267.05 9635,6340.97 ; X1.5@9780.01,6991.05 9780.01,6984.56 9635,6839.55 9635,6340.97 ; 8675,6607.05 8675,6631.89
  Top Layer w27.56: v1(7505,4167.05) v1(7535,4167.05) v1(7755,4167.05) v1(7785,4167.05)
  Top Layer w30: v1(4565,6978.54) v1(4584.2,6978.54) v1(4874.94,6978.54) v1(4894.67,6978.54) 5178.51,6978.54 5265,6892.05 C7.2@5307.44,6892.05 ; U2.A9@5275.94,7067.24 5275.94,7003.54 5307.44,6972.05 ; U2.B9@5394.06,7067.24 5394.06,7001.1 5365,6972.05 5307.44,6972.05 ; H3.48@5485,6667.05 H3.47@5385,6667.05 5307.44,6744.61 C7.2@5307.44,6892.05 ; C7.2@5307.44,6892.05 5307.44,6972.05
  Top Layer w39.37: CN1.5@6444.84,5598.94 6486.73,5557.05 6669.09,5557.05 CN1.14@6710.98,5598.94 6795,5682.96 6795,6372.05 6735,6432.05
  Top Layer w66.93: 8635,6732.05 8700,6667.05 8735,6667.05 H5.48@9022.01,6667.05 H5.47@9122.01,6667.05 9235,6667.05 9535,6367.05 ; U15.2@9891.89,3792.05 9891.89,6162.05 9786.89,6267.05 U10.23@9635,6267.05 ; 9535,6367.05 U10.24@9535,6267.05 U10.23@9635,6267.05 ; 9535,6367.05 9573.65,6328.4 U10.23@9635,6267.05
  Bottom Layer w6: v1(4865,7247.05) 4884.45,7227.6 U6.3@4884.45,7000.12
  Bottom Layer w15: 7988.95,3745 ccw(c8034.41,3745) 8011.68,3705.63 ; 7989,3745.05 7989,3787.05 ; 8011,3706.05 U12.9@8079.49,3667.05 ; SLOT1.45@11560,6317.07 11634.98,6317.07 11685,6267.05 12834.98,6267.05 SLOT2.45@12885,6317.07 ; SLOT1.47@11560,6417.07 11634.98,6417.07 11685,6367.05 12834.98,6367.05 SLOT2.47@12885,6417.07
  Bottom Layer w20: 6390.96,4177.05 6434.49,4133.52 ; 6448.87,4167.05 6434.49,4152.67 6434.49,4133.52 ; U13.7@6599.92,4042.05 6525.96,4042.05 6434.49,4133.52
  Bottom Layer w27.56: 6415,4167.05 6448.87,4167.05 v1(7505,4167.05) v1(7535,4167.05) ; v1(7755,4167.05) v1(7785,4167.05) 7945,4167.05 7989,4123.05 7989,3787.05
  Bottom Layer w39.37: 6415,4167.05 6365,4217.05 6365,5057.05 6495,5187.05 6495,5382.96 CN1.14@6710.98,5598.94 ; USB1.1@6634.81,6690.7 6634.81,6532.24 6755,6412.05
  Bottom Layer w62.99: USB1.1@6634.81,6690.7 6634.81,6752.55 ; 8685,6682.05 8573.95,6793.1 6675.36,6793.1 ; 6634.81,6752.55 6675.36,6793.1 ; 6634.81,6752.55 USB1.5@6634.81,6793.1 6675.36,6793.1
  other v1: 6745,6407.05 6730,6422.05 6760,6422.05 6745,6437.05 8655,6687.05 8700,6692.05 8635,6707.05 8680,6712.05 8615,6727.05 8660,6732.05 8640,6752.05
VCC12: L1.1 R44.1 U19.6 | length 1897.2
  Top Layer w10: R44.1@10614.66,6842.05 10714.66,6942.05 U19.6@10860,6942.05
  Top Layer w30: U19.6@10860,6942.05 10935,6942.05 11133.04,7140.09 11900,7140.09 12210,6830.09 L1.1@12260,6830.09
VCC12L: C40.2 C42.2 L1.2 R45.2 SLOT1.48 SLOT2.48 | length 1844.1
  Top Layer w20: C42.2@12262.56,6442.05 12305,6442.05 v1(12330,6467.05)
  Top Layer w30: L1.2@12260,6754.01 12262.56,6751.45 C42.2@12262.56,6442.05
  Bottom Layer w10: SLOT1.48@11360,6417.07 11435.02,6417.07 11485,6467.05 11635,6467.05 11685,6417.05 12313.4,6417.05 ; SLOT2.48@12684.98,6417.05 12346.6,6417.05 ; 12313.4,6417.05 12330,6433.64 12346.6,6417.05 ; 12313.4,6417.05 12346.6,6417.05
  Bottom Layer w20: 12330,6427.05 12330,6433.64 v1(12330,6467.05)
VCC15: 1.5V.2 C11.2 C14.2 C17.2 R11.2 R12.2 U5.2 U5.4 U8.72 U8.81 U8.90 U8.97 U8.103 U8.110 U8.191 U8.198 U8.204 U8.211 U8.220 U8.229 | length 5951.2
  Top Layer w10: U8.72@4070.82,4737.92 4070.82,4842.05 ; 4070.82,5992.05 U8.229@4070.82,6096.18 ; U8.81@4247.98,4737.92 4247.98,4842.05 ; 4247.99,5992.05 U8.220@4247.99,6096.18 ; U8.90@4425.15,4737.92 4425.15,4842.05 ; 4425.15,5992.05 U8.211@4425.15,6096.18 ; U8.97@4562.94,4737.92 4562.94,4842.05 ; 4562.94,5992.05 U8.204@4562.94,6096.18 ; U8.103@4681.06,4737.92 4681.06,4842.05 ; 4681.06,5992.05 U8.198@4681.06,6096.18 ; U8.110@4818.85,4737.92 4818.85,4842.05 ; 4818.85,5992.05 U8.191@4818.85,6096.18
  Top Layer w30: 4070.82,4842.05 4247.98,4842.05 4364.52,4842.05 ; 4070.82,5992.05 4247.99,5992.05 4365.34,5992.05 ; 4818.85,4842.05 4681.06,4842.05 4562.94,4842.05 4425.15,4842.05 4405.48,4842.05 ; v1(5025,5992.05) v1(5004.07,5992.05) 4818.85,5992.05 4681.06,5992.05 4562.94,5992.05 4425.15,5992.05 4404.66,5992.05 ; 4364.52,4842.05 4385,4862.53 ; 4364.52,4842.05 4405.48,4842.05 ; 4365.34,5992.05 4385,5972.39 ; 4365.34,5992.05 4404.66,5992.05 ; 4385,4862.53 4385,5972.39 ; 4385,4862.53 4405.48,4842.05 ; 4385,5972.39 4404.66,5992.05
  Bottom Layer w10: R12.2@4280.34,5367.05 R11.2@4280.34,5467.05 4280.34,5517.39 4305,5542.05 v1(4380,5542.05)
  Bottom Layer w30: U5.4@4665,7229.55 U5.2@4665,7004.55 4665,6802.68 C14.2@4675.63,6792.05 C17.2@4592.56,6792.05 4592.56,6404.49 5005,5992.05 v1(5025,5992.05)
  other v2: 4635,7272.05
VCC33: 3.3V.2 C1.2 C3.2 C4.2 C6.2 C8.2 C9.2 C10.2 C12.2 C13.2 C15.2 C16.2 C18.2 C19.2 C20.2 C21.2 CARD1.4 H1.4 H4.48 H6.47 R14.2 R15.2 R29.2 R30.2 RN1.1 RN1.2 RN1.3 RN1.4 RN2.6 RN2.7 RN2.8 RN3.1 RN3.2 RN3.3 RN3.4 RN4.5 RN4.6 RN4.7 RN4.8 RN5.5 RN5.6 RN5.7 RN5.8 RN34.5 RN34.6 RN34.7 RN34.8 TF1.4 U1.5 U4.3 U4.7 U4.8 U6.2 U6.4 U7.1 U7.3 U7.9 U7.14 U7.27 U7.43 U7.49 U8.9 U8.22 U8.51 U8.70 U8.92 U8.112 U8.130 U8.148 U8.155 U8.157 U8.172 U8.189 U8.209 U8.231 | length 18362.5
  Top Layer w6: v2(4760,7272.05) 4760.2,7271.85 3.3V.2@4760.2,7246.55
  Top Layer w10: v1(3660,6849.55) 3744.18,6849.55 3745.13,6850.5 ; 3727.79,7142.68 3749.38,7142.68 3755,7148.3 ; 3745.13,7094.37 3755,7104.24 3755,7148.3 ; v1(3755,7202.05) 3755,7148.3 ; U8.51@3755.86,5013.51 v1(3825,5013.51) ; U8.22@3755.86,5584.37 v1(3825,5584.37) ; U8.9@3755.86,5840.28 v1(3825,5840.28) ; U8.70@4031.45,4737.92 v1(4031.45,4807.05) ; v1(4031.45,6027.04) U8.231@4031.45,6096.18 ; 4171.52,6902.05 4174.97,6898.6 U7.14@4174.97,6832.05 ; v1(4238,6357.05) U7.43@4238,6402.05 ; U7.9@4332,6832.05 4332,6900.9 4333.15,6902.05 ; v1(4427,6357.05) U7.49@4427,6402.05 ; U8.92@4464.52,4737.92 v1(4464.52,4807.05) ; v1(4464.52,6027.04) U8.209@4464.52,6096.18 ; 4517.26,6902.05 4521.05,6898.25 U7.3@4521.05,6832.05 ; U7.1@4584,6832.05 4584,6899.64 4586.41,6902.05 ; U8.112@4858.23,4737.92 v1(4858.23,4807.05) ; v1(4858.23,6027.04) U8.189@4858.23,6096.18 ; v1(5045,5013.51) U8.130@5114.14,5013.51 ; v1(5045,5367.84) U8.148@5114.14,5367.84 ; v1(5045,5505.63) U8.155@5114.14,5505.63 ; v1(5045,5545) U8.157@5114.14,5545 ; v1(5045,5840.28) U8.172@5114.14,5840.28 ; 7922.13,6437.39 7921.81,6437.71 CARD1.4@7921.81,6591.26 7921.81,6611.26 7941.81,6631.26 7969.21,6631.26 8013.35,6675.4 TF1.4@8013.35,6718.39
  Top Layer w20: v1(6622.5,6899.55) v1(6642.5,6879.55) 6730,6792.05 6985,6792.05 H6.47@7110,6667.05 7339.66,6437.39 R29.2@7625,6437.39 7922.13,6437.39 R30.2@8020,6437.39 v1(8247.5,6437.39) ; v1(8637.5,6437.05) 8850,6437.05 8955,6332.05 8955,4339.55 8995,4299.55 9217.5,4299.55 9249.57,4331.61 RN34.8@9249.57,4519.81 RN34.7@9249.57,4551.3 RN34.6@9249.57,4582.8 RN34.5@9249.57,4614.29
  Top Layer w30: H4.48@3485,6667.05 3690,6667.05 ; H1.4@3485,7117.05 3575,7117.05 3613.29,7155.34 3715.13,7155.34 3727.79,7142.68 3745.13,7125.34 3745.13,7094.37 3745.13,6902.05 ; v1(4915,6902.05) v1(4890,6902.05) 4586.41,6902.05 4517.26,6902.05 4333.15,6902.05 4171.52,6902.05 3745.13,6902.05 ; 3690,6667.05 v1(3715,6692.05) 3745.13,6722.18 ; 3690,6667.05 3711.86,6667.05 v1(3715,6670.19) 3745.13,6700.32 3745.13,6722.18 ; 3745.13,6722.18 3745.13,6850.5 3745.13,6902.05
  Bottom Layer w6: v2(4760,7272.05) 4936.93,7272.05 U6.4@4975,7233.98 ; C15.2@4973.57,6792.05 C15.2@4985.63,6792.05
  Bottom Layer w10: RN2.6@3669.25,7202.48 RN2.7@3700.75,7202.48 RN2.8@3732.24,7202.48 3732.68,7202.05 v1(3755,7202.05) ; U4.7@3710,7022.66 3710,6972.05 v1(3737.5,6944.55) 3760,6967.05 U4.8@3760,7022.66 ; v1(4085,6897.05) 4095,6887.05 4122.5,6887.05 4135,6874.55 U1.5@4135,6854.65 ; v1(4238,6357.05) 4238,6207.05 4270.83,6174.22 4270.83,6024.61 4265.83,6019.61 ; v1(4427,6357.05) 4427,6027.61 C6.2@4435,6019.6
  Bottom Layer w20: RN5.5@6149.56,5494.81 RN5.6@6149.56,5526.3 RN5.7@6149.56,5557.8 RN5.8@6149.56,5589.29 RN3.1@6149.56,5694.81 RN3.2@6149.56,5726.3 RN3.3@6149.56,5757.8 RN3.4@6149.56,5789.29 RN1.1@6149.56,5894.81 RN1.2@6149.56,5926.3 RN1.3@6149.56,5957.8 RN1.4@6149.56,5989.29 RN4.5@6149.56,6094.81 RN4.6@6149.56,6126.3 RN4.7@6149.56,6157.8 RN4.8@6149.56,6189.29 6149.56,6954.11 6192.5,6997.05 6282.5,6997.05 6332.84,6946.71 R14.2@6460,6946.71 R15.2@6535,6946.71 6575.34,6946.71 v1(6622.5,6899.55) v1(6642.5,6879.55) ; v1(8247.5,6437.39) 8637.16,6437.39 v1(8637.5,6437.05)
  Bottom Layer w30: v1(3715,6692.05) v1(3715,6670.19) 3715,6597.05 3832.44,6479.61 C21.2@3832.44,5817.05 C19.2@3832.44,5417.05 C20.2@3832.44,5017.05 3832.44,4974.62 3992.57,4814.49 C9.2@4035,4814.49 C3.2@4435,4814.49 C8.2@4835,4814.49 4877.43,4814.49 5037.56,4974.62 C13.2@5037.56,5017.05 C16.2@5037.56,5417.05 C10.2@5037.56,5817.05 5037.56,5859.47 4877.43,6019.61 C1.2@4835,6019.6 C6.2@4435,6019.6 4265.83,6019.61 C4.2@4035,6019.6 ; C15.2@4973.57,6792.05 C18.2@4902.56,6792.05 4902.56,6889.49 ; U6.4@4975,7233.98 U6.2@4975,7000.12 4975,6802.68 C15.2@4985.63,6792.05 ; 4902.56,6889.49 v1(4890,6902.05) v1(4915,6902.05) 4902.56,6889.61 4902.56,6889.49
VCCM12: -12V.1 L2.1 U19.4 | length 1666.9
  Top Layer w10: -12V.1@10551.5,6741.65 10596.9,6787.05 10635,6787.05 10680,6742.05 U19.4@10860,6742.05
  Top Layer w30: U19.4@10860,6742.05 10935,6742.05 11205,7012.05 11818.04,7012.05 11985,6845.09 L2.1@11985,6830.09
VCCM12L: C41.1 C43.2 L2.2 R46.2 SLOT1.50 SLOT2.50 | length 1846.9
  Top Layer w20: v1(11915,6467.05) 11940,6442.05 C43.2@11982.44,6442.05
  Top Layer w30: C43.2@11982.44,6442.05 11982.44,6751.45 L2.2@11985,6754.01
  Bottom Layer w10: SLOT1.50@11360,6517.07 11435.02,6517.07 11485,6567.05 11635,6567.05 11685,6517.05 11897.44,6517.05 ; SLOT2.50@12684.98,6517.05 11932.56,6517.05 ; 11897.44,6517.05 11915,6499.49 11932.56,6517.05 ; 11897.44,6517.05 11932.56,6517.05
  Bottom Layer w20: v1(11915,6467.05) 11915,6499.49 11915,6507.05
VG0: H2.7 RN32.2 U8.85 U11.8 | length 607.9
  Top Layer w6: H2.7@3985,4467.05 3985,4470.08 4074.97,4560.05 4188.91,4560.05 4326.73,4697.86 U8.85@4326.73,4737.92
  Bottom Layer w10: RN32.2@7600.75,4581.61 7600.75,4541.3 7635,4507.05 U11.8@7635,4467.05
VG1: H2.8 RN32.1 U8.86 U11.7 | length 844.4
  Top Layer w6: H2.8@3985,4367.05 4035,4417.05 4035,4503.11 4079.94,4548.05 4193.88,4548.05 4346.41,4700.58 U8.86@4346.41,4737.92
  Bottom Layer w10: RN32.1@7632.24,4581.61 7632.24,4539.81 7685,4487.05 7685,4417.05 U11.7@7635,4367.05
VG2: H2.9 RN31.4 U8.87 U11.10 | length 529.3
  Top Layer w6: H2.9@4085,4467.05 4154,4536.05 4198.85,4536.05 4366.1,4703.29 U8.87@4366.1,4737.92
  Bottom Layer w10: U11.10@7735,4467.05 7737.76,4469.81 RN31.4@7737.76,4581.61
VG3: H2.10 RN31.3 U8.88 U11.9 | length 763.5
  Top Layer w6: H2.10@4085,4367.05 4135,4417.05 4135,4500.08 4158.97,4524.05 4203.82,4524.05 4385.78,4706.01 U8.88@4385.78,4737.92
  Bottom Layer w10: U11.9@7735,4367.05 7785,4417.05 7785,4522.05 7769.25,4537.8 RN31.3@7769.25,4581.61
VG4: H2.11 RN31.2 U8.93 U11.12 | length 576.3
  Top Layer w6: H2.11@4185,4467.05 4280.5,4562.54 4370.5,4562.54 4484.2,4676.25 U8.93@4484.2,4737.92
  Bottom Layer w10: RN31.2@7800.75,4581.61 7800.75,4541.3 7835,4507.05 U11.12@7835,4467.05
VG5: H2.12 RN31.1 U8.94 U11.11 | length 812.8
  Top Layer w6: H2.12@4185,4367.05 4235,4417.05 4235,4500.08 4285.47,4550.54 4375.47,4550.54 4503.9,4678.97 U8.94@4503.9,4737.92
  Bottom Layer w10: RN31.1@7832.24,4581.61 7832.24,4539.81 7885,4487.05 7885,4417.05 U11.11@7835,4367.05
VG_SY: C28.2 S1.6 U12.2 | length 2466.5
  Top Layer w10: C28.2@8184.99,3936.93 8184.99,3891.93 8214.73,3862.2 U12.2@8214.74,3745
  Bottom Layer w10: S1.6@6849.71,3762.35 6884.71,3797.36 7024.69,3797.36 7410,3412.05 8265,3412.05 8445,3592.05 8445,3717.05 8355,3807.05 8276.78,3807.05 U12.2@8214.74,3745
VR0: H2.13 RN30.4 U8.95 U11.14 | length 502.4
  Top Layer w6: H2.13@4285,4467.05 4285,4472.05 4351.5,4538.54 4380.44,4538.54 4523.57,4681.68 U8.95@4523.57,4737.92
  Bottom Layer w10: U11.14@7935,4467.05 7937.76,4469.81 RN30.4@7937.76,4581.61
VR1: H2.14 RN30.3 U8.98 U11.13 | length 778.7
  Top Layer w6: H2.14@4285,4367.05 4335,4417.05 4335,4505.08 4356.47,4526.54 4429.5,4526.54 4582.64,4679.68 U8.98@4582.64,4737.92
  Bottom Layer w10: U11.13@7935,4367.05 7985,4417.05 7985,4522.05 7969.25,4537.8 RN30.3@7969.25,4581.61
VR2: H2.15 RN30.2 U8.99 U11.16 | length 490.8
  Top Layer w6: H2.15@4385,4467.05 4386.97,4467.05 4602.31,4682.39 U8.99@4602.31,4737.92
  Bottom Layer w10: RN30.2@8000.75,4581.61 8000.75,4541.3 8035,4507.05 U11.16@8035,4467.05
VR3: H2.16 RN30.1 U8.100 U11.15 | length 726.2
  Top Layer w6: H2.16@4385,4367.05 4435,4417.05 4435,4498.11 4622.01,4685.11 U8.100@4622.01,4737.92
  Bottom Layer w10: RN30.1@8032.24,4581.61 8032.24,4539.81 8085,4487.05 8085,4417.05 U11.15@8035,4367.05
VR4: H2.17 R19.1 U8.101 U11.18 | length 456.1
  Top Layer w6: H2.17@4485,4467.05 4485,4531.14 4641.69,4687.82 U8.101@4641.69,4737.92
  Bottom Layer w10: U11.18@8135,4467.05 R19.1@8135,4587.39
VR5: H2.18 R18.1 U8.104 U11.17 | length 711.6
  Top Layer w6: H2.18@4485,4367.05 4535,4417.05 4535,4500.08 4700.74,4665.82 U8.104@4700.74,4737.92
  Bottom Layer w10: U11.17@8135,4367.05 8185,4417.05 8185,4562.39 R18.1@8210,4587.39
VR_SC: C27.2 S1.5 U12.1 | length 2608.4
  Top Layer w10: U12.1@8304.88,3745 8411.93,3852.05 8445,3852.05 8485,3892.04 C27.2@8485,3936.93
  Bottom Layer w10: S1.5@6585.93,3762.35 6645.62,3822.05 7035,3822.05 7420,3437.05 8255,3437.05 8420,3602.05 8420,3707.05 8382.05,3745 U12.1@8304.88,3745
VSYNC: RN6.7 U12.14 | length 2145.3
  Top Layer w6: U12.14@8034.41,3609.1 8034.41,3492.64 v1(8035,3492.05)
  Bottom Layer w6: RN6.7@6849.56,4467.8 6820.75,4467.8 6802,4449.05 6802,4322.02 6865.97,4258.05 7550.97,4258.05 7807,4002.02 7807,3543.08 7845.03,3505.05 8022,3505.05 v1(8035,3492.05)
WAIT: H7.42 RN25.5 SLOT1.7 SLOT2.7 U9.8 | length 2748.5
  Bottom Layer w6: RN25.5@9320.43,4614.29 9347.76,4614.29 9394,4568.05 9394,4453.96 9456,4391.96 9456,4273.02 9461.97,4267.05 U9.8@9535,4267.05
  Bottom Layer w10: H7.42@10735,4267.05 11185,4267.05 11285,4367.05 11435,4367.05 11485.03,4417.08 SLOT1.7@11560,4417.08 11634.97,4417.08 11685,4367.05 12834.97,4367.05 SLOT2.7@12885,4417.08
WR: H7.36 RN23.7 SLOT1.13 SLOT2.13 U9.14 | length 2750
  Bottom Layer w6: RN23.7@9320.43,4951.3 9345.75,4951.3 9368.03,4929.02 9368.03,4840.99 9426.01,4783 9426.01,4667.55 9530.76,4562.81 U9.14@9535,4567.05
  Bottom Layer w10: H7.36@10735,4567.05 11185,4567.05 11285,4667.05 11435,4667.05 11485.03,4717.08 SLOT1.13@11560,4717.08 11634.97,4717.08 11685,4667.05 12834.97,4667.05 SLOT2.13@12885,4717.08
"": CN1.19 CN1.20 CN1.21 CN1.22 KEY1.0 pad.1 R39.6 R39.7 RN3.8 RN5.4 S1.1 S1.3 SLOT1.0 SLOT2.0 U2.A5 U2.B5 U7.40 U8.17 U8.18 U8.19 U8.20 U8.21 U8.23 U8.32 U8.41 U8.42 U8.149 U8.238 U8.239 U12.0 U12.4 U12.11 U13.1 U13.2 U13.3 U13.8 U14.3 U14.4 U18.5 X1.2 X1.8 X1.SH1 X1.SH2 X1.SH3

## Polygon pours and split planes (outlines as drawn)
GND on Bottom Layer (solid, remove dead copper, pour order 0): 3000,3344.55 10212.5,3344.55 10212.5,7392.05 3000,7392.05
GND on Top Layer (solid, remove dead copper, pour order 1): 3115,3222.05 10120,3222.05 10120,7479.55 3115,7479.55

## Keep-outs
Board Outline Layer:
  lines w10 net "": 3285,4317.05 ccw(c3335,4317.05) 3335,4267.05 5535,4267.05 ccw(c5535,4317.05) 5585,4317.05 5585,7267.05 ccw(c5535,7267.05) 5535,7317.05 3335,7317.05 ccw(c3335,7267.05) 3285,7267.05 3285,4317.05 ; 6085,3430.04 ccw(c6135,3430.04) 6135,3380.04 9972.01,3380.04 ccw(c9972.01,3430.04) 10022.01,3430.04 10022.01,7267.05 ccw(c9972.01,7267.05) 9972.01,7317.05 6135,7317.05 ccw(c6135,7267.05) 6085,7267.05 6085,3430.04 ; 10485,3430.04 ccw(c10535,3430.04) 10535,3380.04 12991.1,3380.04 ccw(c12991.1,3430.04) 13041.1,3430.04 13041.1,7267.05 ccw(c12991.1,7267.05) 12991.1,7317.05 10535,7317.05 ccw(c10535,7267.05) 10485,7267.05 10485,3430.04

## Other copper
Top Layer:
  drawing of 658 lines, arcs and shapes, not listed
Bottom Layer:
  drawing of 946 lines, arcs and shapes, not listed

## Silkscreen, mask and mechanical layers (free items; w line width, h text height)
Top Silkscreen Layer:
  lines w10 net "": 6922.01,4317.05 ccw(c6972.01,4317.05) 6972.01,4267.05 9172.01,4267.05 ccw(c9172.01,4317.05) 9222.01,4317.05 9222.01,7267.05 ccw(c9172.01,7267.05) 9172.01,7317.05 6972.01,7317.05 ccw(c6972.01,7267.05) 6922.01,7267.05 6922.01,4317.05
  text "5V-IN" at 4939.56,7271.59 h57.27 r270
  text "1.5V" at 4564.52,7271.38 h57.45 r270
  text "3.3V" at 4689.52,7271.38 h57.45 r270
  text "5V" at 4814.52,7270.51 h57.45 r270
  text "+12V" at 10655.44,6924.06 h57.45
  text "-12V" at 10655.44,6724.06 h57.45
  text "5V" at 10656.31,6524.06 h57.45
